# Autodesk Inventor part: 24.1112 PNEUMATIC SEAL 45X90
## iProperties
Created: 2007-06
Part Number: 24.1112 PNEUMATIC SEAL 45X90
Material: Default
Document SubType Name: Modeling
Designer: Andy Moles
Density: 1 g/cm^3
Author: Andy Moles
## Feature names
1. Extrusion1
2. Fillet1
